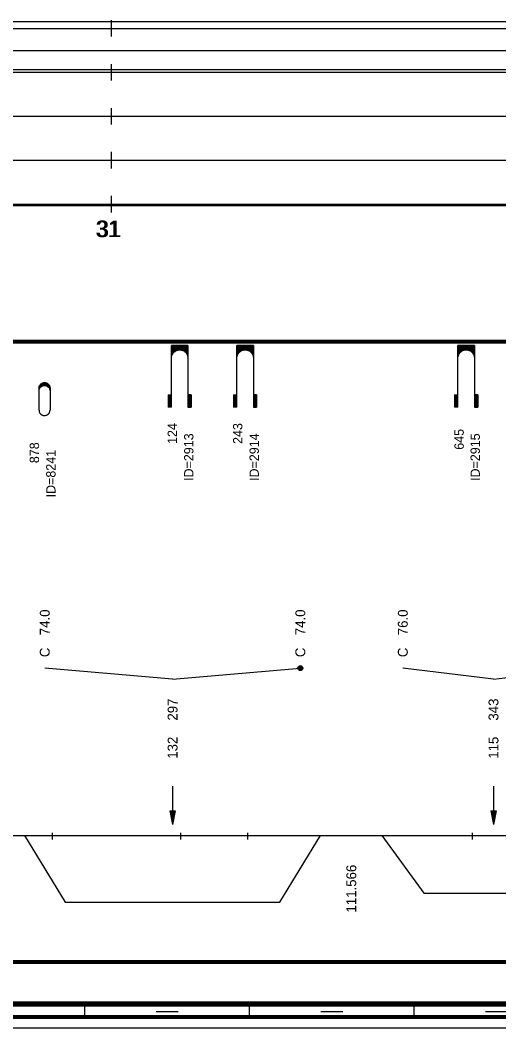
# Model space of a CAD drawing. Extents: x 2 to 10148, y 0 to 380.
# Drawn here: x 3383.3 to 3470.4, y 0 to 183.5 of the extents above; entities that cross this region are included whole.
import ezdxf

# ---------------------------------------------------------------- set-up
doc = ezdxf.new("R2010")
doc.units = 0
for name, color, linetype in [('CARA_S_OBJEKTY', 7, 'Continuous'), ('KRIV1_CARA', 7, 'Continuous'), ('KRIV1_TEXT', 7, 'Continuous'), ('OBJEKTY_TEXT', 7, 'Continuous'), ('OBJEKTY_TVAR', 7, 'Continuous'), ('RAM', 7, 'Continuous'), ('RYCHL_A', 7, 'Continuous'), ('RYCHL_B', 7, 'Continuous'), ('RYCHL_C', 7, 'Continuous'), ('RYCHL_RASTR', 7, 'Continuous'), ('RYCHL_STAN', 7, 'Continuous'), ('STAN_CARA', 7, 'Continuous')]:
    doc.layers.add(name, color=color, linetype=linetype)

msp = doc.modelspace()

# ---------------------------------------------------------------- linework, layer by layer
for p, q in [((3389.06, 35.51), (3389.06, 34.32)), ((3412.42, 35.51), (3412.42, 34.32)), ((3424.63, 35.51), (3424.63, 34.32)), ((3465.55, 35.51), (3465.55, 34.32))]:
    msp.add_line(p, q)
at = {"layer": 'CARA_S_OBJEKTY'}
for p, q in [((3155.54, 125.25), (4045.76, 125.25)), ((3155.54, 125), (4045.76, 125)), ((3155.54, 124.75), (4045.76, 124.75))]:
    msp.add_line(p, q, dxfattribs=at)
at = {"layer": 'KRIV1_CARA'}
for p, q in [((3155.54, 35), (4045.76, 35)), ((3384.03, 35), (3391.43, 22.88)), ((3430.56, 22.88), (3437.96, 35)), ((3449.12, 35), (3456.72, 24.5)), ((3456.72, 24.5), (3482.14, 24.5)), ((3391.43, 22.88), (3430.56, 22.88))]:
    msp.add_line(p, q, dxfattribs=at)
at = {"layer": 'KRIV1_TEXT'}
for p, q in [((3411, 63.5), (3387.73, 65.5)), ((3411, 63.5), (3434.26, 65.5)), ((3469.43, 63.5), (3452.92, 65.5)), ((3469.43, 63.5), (3485.94, 65.5)), ((3411, 44), (3411, 42.2)), ((3469.43, 44), (3469.43, 42.2)), ((3411, 42.2), (3411, 40)), ((3469.43, 42.2), (3469.43, 40)), ((3410.5, 39.5), (3411, 37)), ((3410.5, 39.5), (3411.5, 39.5)), ((3410.6, 39.5), (3411, 37.5)), ((3410.7, 39.5), (3411, 38)), ((3410.8, 39.5), (3411, 38.5)), ((3410.9, 39.5), (3411, 39)), ((3411, 40), (3411, 37)), ((3411.5, 39.5), (3411, 37)), ((3411.4, 39.5), (3411, 37.5)), ((3411.3, 39.5), (3411, 38)), ((3411.2, 39.5), (3411, 38.5)), ((3411.1, 39.5), (3411, 39)), ((3411, 39.5), (3411, 39.5)), ((3411, 39.5), (3411, 39.5)), ((3468.93, 39.5), (3469.43, 37)), ((3468.93, 39.5), (3469.93, 39.5)), ((3469.03, 39.5), (3469.43, 37.5)), ((3469.13, 39.5), (3469.43, 38)), ((3469.23, 39.5), (3469.43, 38.5)), ((3469.33, 39.5), (3469.43, 39)), ((3469.43, 40), (3469.43, 37)), ((3469.93, 39.5), (3469.43, 37)), ((3469.83, 39.5), (3469.43, 37.5)), ((3469.73, 39.5), (3469.43, 38)), ((3469.63, 39.5), (3469.43, 38.5)), ((3469.53, 39.5), (3469.43, 39)), ((3469.43, 39.5), (3469.43, 39.5)), ((3469.43, 39.5), (3469.43, 39.5))]:
    msp.add_line(p, q, dxfattribs=at)
for radius in [0.45, 0.3, 0.15]:
    msp.add_circle((3434.26, 65.5), radius, dxfattribs=at)
at = {"layer": 'OBJEKTY_TVAR'}
for p, q in [((3410.8, 113), (3410.8, 124.25)), ((3413.8, 124.25), (3410.8, 124.25)), ((3410.8, 124.17), (3413.8, 124.17)), ((3410.8, 124.1), (3413.8, 124.1)), ((3410.8, 124.02), (3413.8, 124.02)), ((3410.8, 123.95), (3413.8, 123.95)), ((3410.8, 123.87), (3413.8, 123.87)), ((3410.8, 123.8), (3413.8, 123.8)), ((3410.8, 123.72), (3413.8, 123.72)), ((3410.8, 123.65), (3413.8, 123.65)), ((3410.8, 123.57), (3413.8, 123.57)), ((3410.8, 123.5), (3413.8, 123.5)), ((3410.8, 123.42), (3411.96, 123.42)), ((3410.8, 123.35), (3411.72, 123.35)), ((3410.8, 123.27), (3411.57, 123.27)), ((3410.8, 123.2), (3411.45, 123.2)), ((3410.8, 123.12), (3411.35, 123.12)), ((3410.8, 123.05), (3411.26, 123.05)), ((3410.8, 122.97), (3411.19, 122.97)), ((3411.13, 122.9), (3411.26, 123.05)), ((3411.26, 123.05), (3411.34, 123.12)), ((3411.34, 123.12), (3411.44, 123.19)), ((3411.44, 123.19), (3411.57, 123.27)), ((3411.57, 123.27), (3411.72, 123.35)), ((3411.72, 123.35), (3411.96, 123.42)), ((3411.96, 123.42), (3412.17, 123.46)), ((3412.17, 123.46), (3412.42, 123.46)), ((3412.42, 123.46), (3412.56, 123.44)), ((3412.56, 123.44), (3412.64, 123.42)), ((3412.64, 123.42), (3413.8, 123.42)), ((3412.64, 123.42), (3412.88, 123.35)), ((3412.88, 123.35), (3413.8, 123.35)), ((3412.88, 123.35), (3413.03, 123.27)), ((3413.03, 123.27), (3413.8, 123.27)), ((3413.03, 123.27), (3413.15, 123.2)), ((3413.15, 123.2), (3413.8, 123.2)), ((3413.15, 123.2), (3413.25, 123.12)), ((3413.25, 123.12), (3413.8, 123.12)), ((3413.25, 123.12), (3413.34, 123.05)), ((3413.34, 123.05), (3413.8, 123.05)), ((3413.34, 123.05), (3413.41, 122.97)), ((3413.41, 122.97), (3413.8, 122.97)), ((3413.41, 122.97), (3413.47, 122.9)), ((3413.8, 124.25), (3413.8, 113)), ((3422.71, 113), (3422.71, 124.25)), ((3425.71, 124.25), (3422.71, 124.25)), ((3422.71, 124.17), (3425.71, 124.17)), ((3422.71, 124.1), (3425.71, 124.1)), ((3422.71, 124.02), (3425.71, 124.02)), ((3422.71, 123.95), (3425.71, 123.95)), ((3422.71, 123.87), (3425.71, 123.87)), ((3422.71, 123.8), (3425.71, 123.8)), ((3422.71, 123.72), (3425.71, 123.72)), ((3422.71, 123.65), (3425.71, 123.65)), ((3422.71, 123.57), (3425.71, 123.57)), ((3422.71, 123.5), (3425.71, 123.5)), ((3422.71, 123.42), (3423.87, 123.42)), ((3422.71, 123.35), (3423.63, 123.35)), ((3422.71, 123.27), (3423.48, 123.27)), ((3422.71, 123.2), (3423.36, 123.2)), ((3422.71, 123.12), (3423.26, 123.12)), ((3422.71, 123.05), (3423.17, 123.05)), ((3422.71, 122.97), (3423.1, 122.97)), ((3423.04, 122.9), (3423.17, 123.05)), ((3423.17, 123.05), (3423.25, 123.12)), ((3423.25, 123.12), (3423.35, 123.19)), ((3423.35, 123.19), (3423.48, 123.27)), ((3423.48, 123.27), (3423.63, 123.35)), ((3423.63, 123.35), (3423.87, 123.42)), ((3423.87, 123.42), (3424.08, 123.46)), ((3424.08, 123.46), (3424.33, 123.46)), ((3424.33, 123.46), (3424.47, 123.44)), ((3424.47, 123.44), (3424.55, 123.42)), ((3424.55, 123.42), (3425.71, 123.42)), ((3424.55, 123.42), (3424.79, 123.35)), ((3424.79, 123.35), (3425.71, 123.35)), ((3424.79, 123.35), (3424.94, 123.27)), ((3424.94, 123.27), (3425.71, 123.27)), ((3424.94, 123.27), (3425.06, 123.2)), ((3425.06, 123.2), (3425.71, 123.2)), ((3425.06, 123.2), (3425.16, 123.12)), ((3425.16, 123.12), (3425.71, 123.12)), ((3425.16, 123.12), (3425.25, 123.05)), ((3425.25, 123.05), (3425.71, 123.05)), ((3425.25, 123.05), (3425.32, 122.97)), ((3425.32, 122.97), (3425.71, 122.97)), ((3425.32, 122.97), (3425.38, 122.9)), ((3425.71, 124.25), (3425.71, 113)), ((3462.95, 113), (3462.95, 124.25)), ((3465.95, 124.25), (3462.95, 124.25)), ((3462.95, 124.17), (3465.95, 124.17)), ((3462.95, 124.1), (3465.95, 124.1)), ((3462.95, 124.02), (3465.95, 124.02)), ((3462.95, 123.95), (3465.95, 123.95)), ((3462.95, 123.87), (3465.95, 123.87)), ((3462.95, 123.8), (3465.95, 123.8)), ((3462.95, 123.72), (3465.95, 123.72)), ((3462.95, 123.65), (3465.95, 123.65)), ((3462.95, 123.57), (3465.95, 123.57)), ((3462.95, 123.5), (3465.95, 123.5)), ((3462.95, 123.42), (3464.11, 123.42)), ((3462.95, 123.35), (3463.87, 123.35)), ((3462.95, 123.27), (3463.72, 123.27)), ((3462.95, 123.2), (3463.6, 123.2)), ((3462.95, 123.12), (3463.5, 123.12)), ((3462.95, 123.05), (3463.41, 123.05)), ((3462.95, 122.97), (3463.34, 122.97)), ((3463.28, 122.9), (3463.41, 123.05)), ((3463.41, 123.05), (3463.49, 123.12)), ((3463.49, 123.12), (3463.59, 123.19)), ((3463.59, 123.19), (3463.72, 123.27)), ((3463.72, 123.27), (3463.87, 123.35)), ((3463.87, 123.35), (3464.11, 123.42)), ((3464.11, 123.42), (3464.32, 123.46)), ((3464.32, 123.46), (3464.57, 123.46)), ((3464.57, 123.46), (3464.71, 123.44)), ((3464.71, 123.44), (3464.79, 123.42)), ((3464.79, 123.42), (3465.95, 123.42)), ((3464.79, 123.42), (3465.03, 123.35)), ((3465.03, 123.35), (3465.95, 123.35)), ((3465.03, 123.35), (3465.18, 123.27)), ((3465.18, 123.27), (3465.95, 123.27)), ((3465.18, 123.27), (3465.3, 123.2)), ((3465.3, 123.2), (3465.95, 123.2)), ((3465.3, 123.2), (3465.4, 123.12)), ((3465.4, 123.12), (3465.95, 123.12)), ((3465.4, 123.12), (3465.49, 123.05)), ((3465.49, 123.05), (3465.95, 123.05)), ((3465.49, 123.05), (3465.56, 122.97)), ((3465.56, 122.97), (3465.95, 122.97)), ((3465.56, 122.97), (3465.62, 122.9)), ((3465.95, 124.25), (3465.95, 113)), ((3410.8, 122.9), (3411.13, 122.9)), ((3410.8, 122.82), (3411.07, 122.82)), ((3410.8, 122.75), (3411.02, 122.75)), ((3410.8, 122.67), (3410.98, 122.67)), ((3410.8, 122.6), (3410.94, 122.6)), ((3410.8, 122.52), (3410.91, 122.52)), ((3410.8, 122.45), (3410.88, 122.45)), ((3410.8, 122.37), (3410.86, 122.37)), ((3410.8, 122.3), (3410.84, 122.3)), ((3410.8, 122.22), (3410.82, 122.22)), ((3410.8, 122.15), (3410.81, 122.15)), ((3410.8, 121.97), (3410.81, 122.11)), ((3410.81, 122.11), (3410.83, 122.28)), ((3410.83, 122.28), (3410.88, 122.46)), ((3410.88, 122.46), (3410.95, 122.61)), ((3410.95, 122.61), (3411.02, 122.75)), ((3411.02, 122.75), (3411.13, 122.9)), ((3413.47, 122.9), (3413.79, 122.9)), ((3413.47, 122.9), (3413.53, 122.82)), ((3413.53, 122.82), (3413.8, 122.82)), ((3413.53, 122.82), (3413.62, 122.67)), ((3413.58, 122.75), (3413.8, 122.75)), ((3413.62, 122.67), (3413.8, 122.67)), ((3413.62, 122.67), (3413.69, 122.52)), ((3413.66, 122.6), (3413.8, 122.6)), ((3413.69, 122.52), (3413.8, 122.52)), ((3413.69, 122.52), (3413.74, 122.37)), ((3413.72, 122.45), (3413.8, 122.45)), ((3413.74, 122.37), (3413.8, 122.37)), ((3413.74, 122.37), (3413.78, 122.22)), ((3413.76, 122.3), (3413.8, 122.3)), ((3413.78, 122.22), (3413.8, 122.22)), ((3413.78, 122.22), (3413.8, 121.97)), ((3413.79, 122.15), (3413.8, 122.15)), ((3422.71, 122.9), (3423.04, 122.9)), ((3422.71, 122.82), (3422.98, 122.82)), ((3422.71, 122.75), (3422.93, 122.75)), ((3422.71, 122.67), (3422.89, 122.67)), ((3422.71, 122.6), (3422.85, 122.6)), ((3422.71, 122.52), (3422.82, 122.52)), ((3422.71, 122.45), (3422.79, 122.45)), ((3422.71, 122.37), (3422.77, 122.37)), ((3422.71, 122.3), (3422.75, 122.3)), ((3422.71, 122.22), (3422.73, 122.22)), ((3422.71, 122.15), (3422.72, 122.15)), ((3422.71, 121.97), (3422.72, 122.11)), ((3422.72, 122.11), (3422.74, 122.28)), ((3422.74, 122.28), (3422.79, 122.46)), ((3422.79, 122.46), (3422.86, 122.61)), ((3422.86, 122.61), (3422.93, 122.75)), ((3422.93, 122.75), (3423.04, 122.9)), ((3425.38, 122.9), (3425.7, 122.9)), ((3425.38, 122.9), (3425.44, 122.82)), ((3425.44, 122.82), (3425.71, 122.82)), ((3425.44, 122.82), (3425.53, 122.67)), ((3425.49, 122.75), (3425.71, 122.75)), ((3425.53, 122.67), (3425.71, 122.67)), ((3425.53, 122.67), (3425.6, 122.52)), ((3425.57, 122.6), (3425.71, 122.6)), ((3425.6, 122.52), (3425.71, 122.52)), ((3425.6, 122.52), (3425.65, 122.37)), ((3425.63, 122.45), (3425.71, 122.45)), ((3425.65, 122.37), (3425.71, 122.37)), ((3425.65, 122.37), (3425.69, 122.22)), ((3425.67, 122.3), (3425.71, 122.3)), ((3425.69, 122.22), (3425.71, 122.22)), ((3425.69, 122.22), (3425.71, 121.97)), ((3425.7, 122.15), (3425.71, 122.15)), ((3462.95, 122.9), (3463.28, 122.9)), ((3462.95, 122.82), (3463.22, 122.82)), ((3462.95, 122.75), (3463.17, 122.75)), ((3462.95, 122.67), (3463.13, 122.67)), ((3462.95, 122.6), (3463.09, 122.6)), ((3462.95, 122.52), (3463.06, 122.52)), ((3462.95, 122.45), (3463.03, 122.45)), ((3462.95, 122.37), (3463.01, 122.37)), ((3462.95, 122.3), (3462.99, 122.3)), ((3462.95, 122.22), (3462.97, 122.22)), ((3462.95, 122.15), (3462.96, 122.15)), ((3462.95, 121.97), (3462.96, 122.11)), ((3462.96, 122.11), (3462.98, 122.28)), ((3462.98, 122.28), (3463.03, 122.46)), ((3463.03, 122.46), (3463.1, 122.61)), ((3463.1, 122.61), (3463.17, 122.75)), ((3463.17, 122.75), (3463.28, 122.9)), ((3465.62, 122.9), (3465.94, 122.9)), ((3465.62, 122.9), (3465.68, 122.82)), ((3465.68, 122.82), (3465.95, 122.82)), ((3465.68, 122.82), (3465.77, 122.67)), ((3465.73, 122.75), (3465.95, 122.75)), ((3465.77, 122.67), (3465.95, 122.67)), ((3465.77, 122.67), (3465.84, 122.52)), ((3465.81, 122.6), (3465.95, 122.6)), ((3465.84, 122.52), (3465.95, 122.52)), ((3465.84, 122.52), (3465.89, 122.37)), ((3465.87, 122.45), (3465.95, 122.45)), ((3465.89, 122.37), (3465.95, 122.37)), ((3465.89, 122.37), (3465.93, 122.22)), ((3465.91, 122.3), (3465.95, 122.3)), ((3465.93, 122.22), (3465.95, 122.22)), ((3465.93, 122.22), (3465.95, 121.97)), ((3465.94, 122.15), (3465.95, 122.15)), ((3387.33, 117.43), (3387.45, 117.47)), ((3387.38, 117.45), (3388, 117.45)), ((3387.45, 117.47), (3387.59, 117.49)), ((3387.59, 117.49), (3387.7, 117.5)), ((3387.7, 117.5), (3387.83, 117.49)), ((3387.83, 117.49), (3387.96, 117.46)), ((3387.96, 117.46), (3388.07, 117.43)), ((3386.69, 116.5), (3386.7, 116.65)), ((3386.69, 116.55), (3386.87, 116.55)), ((3386.69, 112.5), (3386.69, 116.5)), ((3386.69, 116.5), (3386.84, 116.5)), ((3386.69, 116.45), (3386.81, 116.45)), ((3386.69, 116.4), (3386.78, 116.4)), ((3386.69, 116.35), (3386.76, 116.35)), ((3386.69, 116.3), (3386.74, 116.3)), ((3386.69, 116.25), (3386.73, 116.25)), ((3386.69, 116.2), (3386.72, 116.2)), ((3386.69, 116.15), (3386.71, 116.15)), ((3386.69, 115.98), (3386.7, 116.13)), ((3386.69, 116.1), (3386.7, 116.1)), ((3386.7, 116.65), (3386.74, 116.81)), ((3386.7, 116.65), (3386.95, 116.65)), ((3386.7, 116.6), (3386.91, 116.6)), ((3386.7, 116.13), (3386.74, 116.28)), ((3386.71, 116.7), (3387, 116.7)), ((3386.72, 116.75), (3387.06, 116.75)), ((3386.74, 116.81), (3386.8, 116.95)), ((3386.74, 116.8), (3387.12, 116.8)), ((3386.74, 116.28), (3386.8, 116.43)), ((3386.75, 116.85), (3387.2, 116.85)), ((3386.77, 116.9), (3387.31, 116.9)), ((3386.8, 116.95), (3386.86, 117.06)), ((3386.8, 116.95), (3387.46, 116.95)), ((3386.8, 116.43), (3386.86, 116.53)), ((3386.82, 117), (3388.56, 117)), ((3386.85, 117.05), (3388.53, 117.05)), ((3386.86, 117.06), (3386.95, 117.18)), ((3386.86, 116.53), (3386.95, 116.65)), ((3386.89, 117.1), (3388.49, 117.1)), ((3386.93, 117.15), (3388.45, 117.15)), ((3386.95, 117.18), (3387.04, 117.26)), ((3386.95, 116.65), (3387.04, 116.74)), ((3386.98, 117.2), (3388.4, 117.2)), ((3387.03, 117.25), (3388.35, 117.25)), ((3387.04, 117.26), (3387.17, 117.35)), ((3387.04, 116.74), (3387.17, 116.83)), ((3387.09, 117.3), (3388.29, 117.3)), ((3387.16, 117.35), (3388.22, 117.35)), ((3387.17, 117.35), (3387.3, 117.42)), ((3387.17, 116.83), (3387.3, 116.9)), ((3387.25, 117.4), (3388.13, 117.4)), ((3387.3, 117.42), (3387.33, 117.43)), ((3387.3, 116.9), (3387.33, 116.91)), ((3387.33, 116.91), (3387.45, 116.95)), ((3387.45, 116.95), (3387.59, 116.97)), ((3387.59, 116.97), (3387.7, 116.98)), ((3387.7, 116.98), (3387.83, 116.97)), ((3387.83, 116.97), (3387.96, 116.94)), ((3387.92, 116.95), (3388.58, 116.95)), ((3387.96, 116.94), (3388.07, 116.9)), ((3388.07, 117.43), (3388.18, 117.37)), ((3388.07, 116.9), (3388.61, 116.9)), ((3388.07, 116.9), (3388.18, 116.85)), ((3388.18, 117.37), (3388.25, 117.32)), ((3388.18, 116.85), (3388.63, 116.85)), ((3388.18, 116.85), (3388.25, 116.8)), ((3388.25, 117.32), (3388.4, 117.21)), ((3388.25, 116.8), (3388.4, 116.68)), ((3388.26, 116.8), (3388.64, 116.8)), ((3388.32, 116.75), (3388.66, 116.75)), ((3388.38, 116.7), (3388.67, 116.7)), ((3388.4, 117.21), (3388.48, 117.11)), ((3388.4, 116.68), (3388.48, 116.59)), ((3388.43, 116.65), (3388.68, 116.65)), ((3388.47, 116.6), (3388.68, 116.6)), ((3388.48, 117.11), (3388.57, 116.98)), ((3388.48, 116.59), (3388.57, 116.46)), ((3388.51, 116.55), (3388.69, 116.55)), ((3388.54, 116.5), (3388.69, 116.5)), ((3388.57, 116.98), (3388.61, 116.89)), ((3388.57, 116.46), (3388.61, 116.37)), ((3388.57, 116.45), (3388.69, 116.45)), ((3388.6, 116.4), (3388.69, 116.4)), ((3388.61, 116.89), (3388.65, 116.77)), ((3388.61, 116.37), (3388.65, 116.24)), ((3388.62, 116.35), (3388.69, 116.35)), ((3388.64, 116.3), (3388.69, 116.3)), ((3388.65, 116.77), (3388.68, 116.65)), ((3388.65, 116.25), (3388.69, 116.25)), ((3388.65, 116.24), (3388.68, 116.13)), ((3388.66, 116.2), (3388.69, 116.2)), ((3388.67, 116.15), (3388.69, 116.15)), ((3388.68, 116.65), (3388.69, 116.56)), ((3388.68, 116.13), (3388.69, 116.03)), ((3388.68, 116.1), (3388.69, 116.1)), ((3388.69, 116.56), (3388.69, 116.5)), ((3388.69, 116.5), (3388.69, 112.5)), ((3388.69, 116.03), (3388.69, 115.98)), ((3410.2, 115.25), (3410.8, 115.25)), ((3410.2, 115.25), (3410.2, 113)), ((3410.27, 115.25), (3410.27, 113)), ((3410.35, 115.25), (3410.35, 113)), ((3410.42, 115.25), (3410.42, 113)), ((3410.5, 115.25), (3410.5, 113)), ((3410.57, 115.25), (3410.57, 113)), ((3410.65, 115.25), (3410.65, 113)), ((3410.72, 115.25), (3410.72, 113)), ((3414.4, 115.25), (3413.8, 115.25)), ((3413.88, 115.25), (3413.88, 113)), ((3413.95, 115.25), (3413.95, 113)), ((3414.03, 115.25), (3414.03, 113)), ((3414.1, 115.25), (3414.1, 113)), ((3414.18, 115.25), (3414.18, 113)), ((3414.25, 115.25), (3414.25, 113)), ((3414.33, 115.25), (3414.33, 113)), ((3414.4, 115.25), (3414.4, 113)), ((3422.11, 115.25), (3422.71, 115.25)), ((3422.11, 115.25), (3422.11, 113)), ((3422.18, 115.25), (3422.18, 113)), ((3422.26, 115.25), (3422.26, 113)), ((3422.33, 115.25), (3422.33, 113)), ((3422.41, 115.25), (3422.41, 113)), ((3422.48, 115.25), (3422.48, 113)), ((3422.56, 115.25), (3422.56, 113)), ((3422.63, 115.25), (3422.63, 113)), ((3426.31, 115.25), (3425.71, 115.25)), ((3425.79, 115.25), (3425.79, 113)), ((3425.86, 115.25), (3425.86, 113)), ((3425.94, 115.25), (3425.94, 113)), ((3426.01, 115.25), (3426.01, 113)), ((3426.09, 115.25), (3426.09, 113)), ((3426.16, 115.25), (3426.16, 113)), ((3426.24, 115.25), (3426.24, 113)), ((3426.31, 115.25), (3426.31, 113)), ((3462.35, 115.25), (3462.95, 115.25)), ((3462.35, 115.25), (3462.35, 113)), ((3462.42, 115.25), (3462.42, 113)), ((3462.5, 115.25), (3462.5, 113)), ((3462.57, 115.25), (3462.57, 113)), ((3462.65, 115.25), (3462.65, 113)), ((3462.72, 115.25), (3462.72, 113)), ((3462.8, 115.25), (3462.8, 113)), ((3462.87, 115.25), (3462.87, 113)), ((3466.55, 115.25), (3465.95, 115.25)), ((3466.03, 115.25), (3466.03, 113)), ((3466.1, 115.25), (3466.1, 113)), ((3466.18, 115.25), (3466.18, 113)), ((3466.25, 115.25), (3466.25, 113)), ((3466.33, 115.25), (3466.33, 113)), ((3466.4, 115.25), (3466.4, 113)), ((3466.48, 115.25), (3466.48, 113)), ((3466.55, 115.25), (3466.55, 113)), ((3386.69, 112.5), (3386.7, 112.35)), ((3386.7, 112.35), (3386.74, 112.2)), ((3386.74, 112.2), (3386.8, 112.05)), ((3386.8, 112.05), (3386.86, 111.95)), ((3386.86, 111.95), (3386.95, 111.83)), ((3388.48, 111.9), (3388.57, 112.02)), ((3388.57, 112.02), (3388.61, 112.11)), ((3388.61, 112.11), (3388.65, 112.24)), ((3388.65, 112.24), (3388.68, 112.35)), ((3388.68, 112.35), (3388.69, 112.45)), ((3388.69, 112.45), (3388.69, 112.5)), ((3410.8, 113), (3410.2, 113)), ((3413.8, 113), (3414.4, 113)), ((3422.71, 113), (3422.11, 113)), ((3425.71, 113), (3426.31, 113)), ((3462.95, 113), (3462.35, 113)), ((3465.95, 113), (3466.55, 113)), ((3386.95, 111.83), (3387.04, 111.74)), ((3387.04, 111.74), (3387.17, 111.65)), ((3387.17, 111.65), (3387.3, 111.58)), ((3387.3, 111.58), (3387.33, 111.57)), ((3387.33, 111.57), (3387.45, 111.53)), ((3387.45, 111.53), (3387.59, 111.51)), ((3387.59, 111.51), (3387.7, 111.5)), ((3387.7, 111.5), (3387.83, 111.51)), ((3387.83, 111.51), (3387.96, 111.54)), ((3387.96, 111.54), (3388.07, 111.58)), ((3388.07, 111.58), (3388.18, 111.63)), ((3388.18, 111.63), (3388.25, 111.68)), ((3388.25, 111.68), (3388.4, 111.8)), ((3388.4, 111.8), (3388.48, 111.9))]:
    msp.add_line(p, q, dxfattribs=at)
at = {"layer": 'RAM'}
for p, q in [((3155.54, 4.75), (4045.76, 4.75)), ((3155.54, 4.5), (4045.76, 4.5)), ((3155.54, 4.25), (4045.76, 4.25)), ((3155.54, 4), (4045.76, 4)), ((3395, 2), (3395, 4)), ((3425, 2), (3425, 4)), ((3455, 2), (3455, 4)), ((3155.54, 2.25), (4045.76, 2.25)), ((3155.54, 2), (4045.76, 2)), ((3408, 3), (3412, 3)), ((3438, 3), (3442, 3)), ((3468, 3), (3472, 3)), ((3155.54, 1.75), (4045.76, 1.75)), ((3155.54, 0), (4045.76, 0))]:
    msp.add_line(p, q, dxfattribs=at)
at = {"layer": 'RYCHL_A'}
msp.add_line((3156.9, 174.5), (3782.41, 174.5), dxfattribs=at)
at = {"layer": 'RYCHL_B'}
msp.add_line((3155.54, 178), (3664.85, 178), dxfattribs=at)
at = {"layer": 'RYCHL_C'}
msp.add_line((3155.54, 183.25), (3570.27, 183.25), dxfattribs=at)
at = {"layer": 'RYCHL_RASTR'}
for p, q in [((3399.91, 180.5), (3399.91, 183.5)), ((3155.54, 182), (4047.3, 182)), ((3399.91, 172.5), (3399.91, 175.5)), ((3155.54, 174), (4047.27, 174)), ((3399.91, 164.5), (3399.91, 167.5)), ((3155.54, 166), (4047.1, 166)), ((3155.54, 158), (4047.25, 158)), ((3399.91, 156.5), (3399.91, 159.5)), ((3399.91, 148.5), (3399.91, 151.5)), ((3155.54, 150), (4045.76, 150)), ((3155.54, 149.75), (4045.76, 149.75))]:
    msp.add_line(p, q, dxfattribs=at)
at = {"layer": 'STAN_CARA'}
for p, q in [((3301.41, 12.25), (3798.41, 12.25)), ((3301.41, 12), (3798.41, 12)), ((3301.41, 12), (3798.41, 12)), ((3301.41, 11.75), (3798.41, 11.75))]:
    msp.add_line(p, q, dxfattribs=at)

# ---------------------------------------------------------------- texts
at = {"layer": 'KRIV1_TEXT'}
for s, p in [('74.0', (3388.63, 71.5)), ('74.0', (3435.16, 71.5)), ('76.0', (3453.82, 71.5)), ('C', (3388.63, 67.5)), ('C', (3435.16, 67.5)), ('C', (3453.82, 67.5)), ('297', (3411.9, 55.95)), ('343', (3470.33, 55.95)), ('132', (3411.9, 49)), ('115', (3470.33, 49)), ('111.566', (3444.44, 21))]:
    msp.add_text(s, height=1.8, rotation=90, dxfattribs=at).set_placement(p)
at = {"layer": 'OBJEKTY_TEXT'}
for s, p in [('124', (3411.8, 106.33)), ('243', (3423.71, 106.33)), ('645', (3464.02, 105.27)), ('878', (3386.69, 102.83)), ('ID=2913', (3414.8, 99.59)), ('ID=2914', (3426.71, 99.59)), ('ID=2915', (3466.95, 99.59)), ('ID=8241', (3389.69, 96.59))]:
    msp.add_text(s, height=1.7, rotation=90, dxfattribs=at).set_placement(p)
at = {"layer": 'RYCHL_STAN'}
for p in [(3396.97, 144), (3397.22, 144)]:
    msp.add_text('31', height=3, dxfattribs=at).set_placement(p)

doc.saveas('drawing.dxf')
